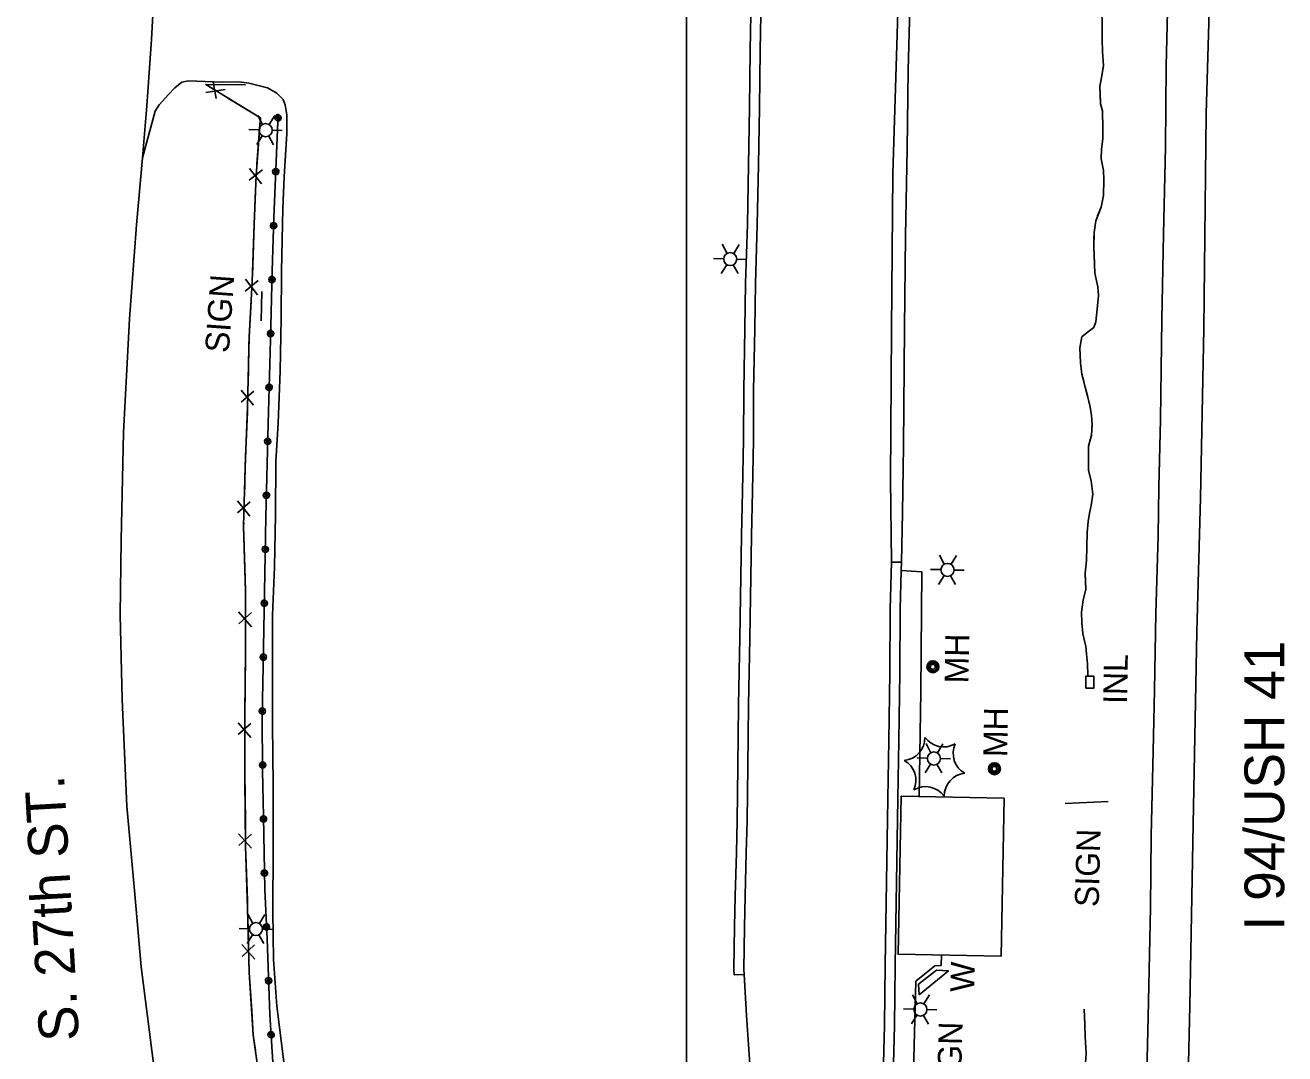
# Model space of a CAD drawing. Extents: x 591954 to 597000, y 198576 to 213500.
# Drawn here: x 593833.7 to 594150.4, y 210712.6 to 210971.1 of the extents above; entities that cross this region are included whole.
import ezdxf

# ---------------------------------------------------------------- set-up
doc = ezdxf.new("R2010")
doc.units = 0
for name, color, linetype in [('1', 7, 'Continuous'), ('Level 10', 7, 'Continuous'), ('Level 11', 7, 'Continuous'), ('Level 12', 7, 'Continuous'), ('Level 14', 7, 'Continuous'), ('Level 15', 7, 'Continuous'), ('Level 16', 7, 'Continuous'), ('Level 17', 7, 'Continuous'), ('Level 18', 7, 'Continuous'), ('Level 19', 7, 'Continuous')]:
    doc.layers.add(name, color=color, linetype=linetype)

msp = doc.modelspace()

# ---------------------------------------------------------------- linework, layer by layer
at = {"layer": 'Level 10'}
msp.add_line((594000, 210000), (594000, 211500), dxfattribs=at)
at = {"layer": 'Level 11'}
for points in [[(594121.44, 210459.17), (594122.25, 210498.37), (594123.17, 210553.35), (594124.43, 210619.5), (594125, 210654.8), (594125.89, 210695.68), (594126.54, 210724.61), (594127.4, 210770.31), (594128.28, 210818.66), (594129.2, 210852.3), (594130.02, 210894.89), (594130.64, 210948.86), (594131.88, 210991.76), (594132.98, 211045.17), (594133.71, 211089.02), (594134.68, 211134.48), (594135.32, 211176), (594136.16, 211221.31), (594137.06, 211262.73), (594137.74, 211300.23), (594138.56, 211351.93)], [(594104.77, 211349.8), (594099.35, 211323.85), (594093.93, 211299.6), (594085.43, 211259.76), (594076, 211209.29), (594068.36, 211162.42), (594064.4, 211134.4), (594060.86, 211102.94), (594058.46, 211075.99), (594056.32, 211045.98), (594054.89, 211024.24), (594053.66, 210994.17), (594052.93, 210968.84), (594051.87, 210933.79), (594051.53, 210894.51), (594051.26, 210856.92), (594051.49, 210836.18)], [(593863.15, 210937.74), (593864.28, 210950.85), (593865.4, 210967.49), (593866.62, 210989.24), (593867.33, 210996.42)], [(594014.42, 210732.48), (594014.39, 210733.85), (594014.57, 210744.41), (594014.72, 210752.24), (594015, 210763.12), (594015.21, 210771.1), (594015.38, 210784.79), (594015.52, 210800.21), (594015.85, 210817.05), (594016.3, 210842.78), (594016.56, 210853.97), (594016.79, 210866.85), (594016.84, 210879.33), (594017.12, 210894.76), (594017.3, 210906.19), (594017.77, 210920.93), (594018.05, 210935.99), (594018.28, 210950.31), (594018.46, 210964.8), (594018.71, 210978.26)], [(594015.96, 210964.84), (594016.21, 210978.31)], [(594015.96, 210964.84), (594016.21, 210978.31)], [(594053.99, 210836.12), (594054.29, 210848.54), (594054.54, 210865.38), (594054.75, 210894.94), (594055, 210918.2), (594055.46, 210940.01), (594055.68, 210959.83), (594056.21, 210978.5)], [(594120.95, 210978.02), (594120.6, 210960.88), (594120.4, 210940.43), (594119.89, 210918.56), (594119.5, 210897.15)], [(594015.78, 210950.34), (594015.96, 210964.84)], [(594015.78, 210950.34), (594015.96, 210964.84)], [(594015.55, 210936.03), (594015.78, 210950.34)], [(594015.55, 210936.03), (594015.78, 210950.34)], [(593942.07, 210448.25), (593930.85, 210481.68), (593922.36, 210504.92), (593910.35, 210541.32), (593899.7, 210573.1), (593890.09, 210602.43), (593883.59, 210625.68), (593877.84, 210646.9), (593873.2, 210666.64), (593869.3, 210687.68), (593866.01, 210709.44), (593862.8, 210734.46), (593861.17, 210753.61), (593859.27, 210774.78), (593858.05, 210801.65), (593857.58, 210822.9), (593857.85, 210841.64), (593858.43, 210868.75), (593859.89, 210897.29), (593861.7, 210920.91), (593863.15, 210937.74)], [(594015.27, 210920.99), (594015.55, 210936.03)], [(594015.27, 210920.99), (594015.55, 210936.03)], [(594014.8, 210906.25), (594015.27, 210920.99)], [(594014.8, 210906.25), (594015.27, 210920.99)], [(594014.62, 210894.8), (594014.8, 210906.25)], [(594014.62, 210894.8), (594014.8, 210906.25)], [(594119.5, 210897.15), (594119.11, 210872.03), (594118.75, 210854.96), (594118.55, 210842.77), (594117.96, 210823.25), (594117.65, 210803.96), (594117.31, 210788.66), (594116.78, 210767.34), (594116.67, 210749.31), (594116.07, 210721.82), (594115.43, 210697.32), (594115.23, 210679.05), (594114.7, 210660.36), (594114.36, 210644.35), (594114.05, 210623.86), (594113.82, 210608.1), (594113.47, 210586.67), (594113.12, 210567.42), (594112.64, 210548.64), (594112.24, 210528.59), (594111.95, 210511.33), (594111.37, 210491), (594111.28, 210469.69), (594111.11, 210459.41)], [(594014.34, 210879.36), (594014.62, 210894.8)], [(594014.34, 210879.36), (594014.62, 210894.8)], [(594014.29, 210866.88), (594014.34, 210879.36)], [(594014.29, 210866.88), (594014.34, 210879.36)], [(594014.06, 210854.02), (594014.29, 210866.88)], [(594014.06, 210854.02), (594014.29, 210866.88)], [(594013.8, 210842.84), (594014.06, 210854.02)], [(594013.8, 210842.84), (594014.06, 210854.02)], [(594013.35, 210817.09), (594013.8, 210842.84)], [(594013.35, 210817.09), (594013.8, 210842.84)], [(594051.49, 210836.18), (594051.21, 210824.34), (594051.08, 210808.43), (594050.81, 210791.35), (594050.62, 210776.77), (594049.9, 210734.81), (594049.73, 210719.74), (594049.4, 210706.94), (594049.33, 210700.84), (594049.22, 210695.93)], [(594051.49, 210836.18), (594053.89, 210836.13), (594053.99, 210836.12), (594053.94, 210834.04)], [(594053.94, 210834.04), (594053.71, 210824.3), (594053.58, 210808.4), (594053.31, 210791.31), (594053.12, 210776.73), (594052.4, 210734.78), (594052.23, 210719.69), (594051.9, 210706.9), (594051.83, 210700.8), (594051.72, 210695.87)], [(594013.02, 210800.24), (594013.35, 210817.09)], [(594013.02, 210800.24), (594013.35, 210817.09)], [(594012.88, 210784.81), (594013.02, 210800.24)], [(594012.88, 210784.81), (594013.02, 210800.24)], [(594012.71, 210771.15), (594012.88, 210784.81)], [(594012.71, 210771.15), (594012.88, 210784.81)], [(594012.5, 210763.18), (594012.71, 210771.15)], [(594012.5, 210763.18), (594012.71, 210771.15)], [(594012.22, 210752.3), (594012.5, 210763.18)], [(594012.22, 210752.3), (594012.5, 210763.18)], [(594012.07, 210744.46), (594012.22, 210752.3)], [(594012.07, 210744.46), (594012.22, 210752.3)], [(594011.89, 210733.84), (594012.07, 210744.46)], [(594011.89, 210733.84), (594012.07, 210744.46)], [(594011.92, 210732.43), (594011.89, 210733.84)], [(594011.92, 210732.43), (594011.89, 210733.84)], [(594014.42, 210732.48), (594012.02, 210732.44), (594011.92, 210732.43)], [(594026.41, 210581.46), (594024.84, 210592.23), (594023.17, 210610.08), (594022.08, 210626.74), (594021.09, 210639.08), (594019.43, 210662.48), (594016.8, 210696.59), (594015.07, 210722.2), (594014.42, 210732.48)]]:
    msp.add_lwpolyline(points, dxfattribs=at)
at = {"layer": 'Level 12'}
msp.add_lwpolyline([(594079.87, 210776.86), (594079.11, 210737.11), (594053.19, 210737.61), (594053.95, 210777.35), (594079.87, 210776.86)], dxfattribs=at)
at = {"layer": 'Level 14'}
for p, q in [((593893.34, 210946.16), (593892.15, 210948.46)), ((593895.05, 210946.15), (593896.41, 210948.38)), ((593892.51, 210944.8), (593889.91, 210944.87)), ((593893.27, 210943.3), (593891.9, 210941.11)), ((593894.9, 210943.26), (593896.15, 210941.08)), ((593895.78, 210944.71), (593898.3, 210944.64)), ((594010.15, 210913.76), (594008.95, 210916.06)), ((594011.85, 210913.75), (594013.22, 210915.98)), ((594009.32, 210912.4), (594006.71, 210912.47)), ((594012.59, 210912.3), (594015.11, 210912.24)), ((594010.07, 210910.9), (594008.71, 210908.71)), ((594011.71, 210910.86), (594012.95, 210908.68)), ((594064.79, 210835.62), (594063.59, 210837.92)), ((594066.49, 210835.61), (594067.85, 210837.84)), ((594063.95, 210834.26), (594061.35, 210834.33)), ((594064.71, 210832.76), (594063.35, 210830.57)), ((594066.34, 210832.72), (594067.59, 210830.54)), ((594067.23, 210834.16), (594069.75, 210834.1)), ((594061.39, 210788.23), (594060.19, 210790.53)), ((594063.09, 210788.22), (594064.45, 210790.45)), ((594060.55, 210786.86), (594057.95, 210786.94)), ((594061.31, 210785.37), (594059.94, 210783.18)), ((594062.94, 210785.33), (594064.19, 210783.15)), ((594063.82, 210786.77), (594066.34, 210786.71)), ((593890.9, 210745.36), (593889.7, 210747.66)), ((593892.6, 210745.35), (593893.96, 210747.58)), ((593890.06, 210743.99), (593887.46, 210744.07)), ((593893.34, 210743.9), (593895.86, 210743.84)), ((593890.82, 210742.5), (593889.46, 210740.31)), ((593892.45, 210742.46), (593893.7, 210740.28)), ((594057.97, 210725.13), (594056.77, 210727.43)), ((594059.67, 210725.12), (594061.04, 210727.35)), ((594057.13, 210723.77), (594054.53, 210723.84)), ((594057.89, 210722.28), (594056.53, 210720.09)), ((594059.53, 210722.23), (594060.77, 210720.05)), ((594060.41, 210723.68), (594062.93, 210723.61))]:
    msp.add_line(p, q, dxfattribs=at)
for points in [[(593892.98, 210896.77), (593893.17, 210904.19)], [(594105.99, 210775.96), (594095.2, 210775.52)]]:
    msp.add_lwpolyline(points, dxfattribs=at)
for centre in [(593894.14, 210944.73), (594010.95, 210912.33), (594065.59, 210834.19), (594062.18, 210786.8), (593891.7, 210743.93), (594058.77, 210723.7)]:
    msp.add_circle(centre, 1.64, dxfattribs=at)
at = {"layer": 'Level 15'}
for p, q in [((593880.95, 210956.83), (593881.68, 210952.67)), ((593879.11, 210954.16), (593883.97, 210954.98)), ((593893.31, 210934.74), (593889.98, 210932.14)), ((593890.09, 210935.1), (593893.11, 210931.21)), ((593892.26, 210906.92), (593888.95, 210904.29)), ((593889.04, 210907.25), (593892.08, 210903.37)), ((593887.96, 210879.37), (593891.11, 210875.58)), ((593891.19, 210879.12), (593887.96, 210876.4)), ((593890.28, 210851.27), (593887.03, 210848.56)), ((593887.05, 210851.53), (593890.18, 210847.73)), ((593887.33, 210823.64), (593890.55, 210819.91)), ((593890.57, 210823.46), (593887.39, 210820.67)), ((593887.2, 210795.77), (593890.43, 210792.05)), ((593890.43, 210795.6), (593887.26, 210792.81)), ((593887.33, 210767.89), (593890.62, 210764.22)), ((593890.57, 210767.76), (593887.43, 210764.93)), ((593888.11, 210740.02), (593891.44, 210736.39)), ((593891.35, 210739.93), (593888.25, 210737.05))]:
    msp.add_line(p, q, dxfattribs=at)
for points in [[(593889.06, 210956.14), (593879.07, 210956.23), (593892.83, 210947.81), (593891.73, 210933.39), (593891.23, 210921.11), (593890.75, 210906.69), (593890, 210892.79), (593889.6, 210875.1), (593889.02, 210860.04), (593888.61, 210845.19), (593889.09, 210828.85), (593889.03, 210812.68), (593888.94, 210797.15), (593888.93, 210781.49), (593889.11, 210764.75), (593889.6, 210749.07), (593890.03, 210733.04), (593891.01, 210717.34), (593892.91, 210703.57)], [(593889.06, 210956.14), (593879.11, 210956.23)], [(593884.64, 210952.81), (593892.83, 210947.81), (593892.7, 210946.09)], [(593892.7, 210946.09), (593891.94, 210936.16)], [(593891.57, 210929.59), (593891.23, 210921.11), (593891.14, 210918.27)], [(593891.14, 210918.27), (593890.81, 210908.32)], [(593890.49, 210901.75), (593890, 210892.79), (593889.95, 210890.44)], [(593889.95, 210890.44), (593889.72, 210880.49)], [(593889.55, 210873.91), (593889.11, 210862.6)], [(593889.11, 210862.6), (593889.02, 210860.04), (593888.82, 210852.64)], [(593888.64, 210846.06), (593888.61, 210845.19), (593888.92, 210834.75)], [(593888.92, 210834.75), (593889.09, 210828.85), (593889.07, 210824.79)], [(593889.05, 210818.21), (593889.03, 210812.68), (593888.99, 210806.89)], [(593888.99, 210806.89), (593888.94, 210797.15), (593888.94, 210796.93)], [(594100.4, 210804.49), (594102.4, 210804.48), (594102.41, 210807.48), (594100.41, 210807.49), (594100.4, 210804.49)], [(593888.93, 210790.35), (593888.93, 210781.49), (593888.96, 210779.03)], [(593888.96, 210779.03), (593889.06, 210769.07)], [(593889.18, 210762.49), (593889.54, 210751.18)], [(593889.54, 210751.18), (593889.6, 210749.07), (593889.81, 210741.22)], [(593889.99, 210734.64), (593890.03, 210733.04), (593890.64, 210723.34)], [(594058.46, 210727.36), (594065.8, 210733.41), (594062.83, 210733.62), (594058.28, 210730.06), (594058.46, 210727.36)], [(593890.64, 210723.34), (593891.01, 210717.34), (593891.55, 210713.43)]]:
    msp.add_lwpolyline(points, dxfattribs=at)
at = {"layer": 'Level 16'}
for centre, radius in [((594061.92, 210809.85), 1.5), ((594061.92, 210809.85), 1.22), ((594061.92, 210809.83), 0.968), ((594061.89, 210809.83), 0.605), ((594077.4, 210784.22), 1.5), ((594077.4, 210784.22), 1.22), ((594077.4, 210784.21), 0.968), ((594077.37, 210784.2), 0.605)]:
    msp.add_circle(centre, radius, dxfattribs=at)
at = {"layer": 'Level 17'}
for points in [[(593898.52, 210952.46), (593896.93, 210954.06), (593894.63, 210955.34), (593889.87, 210956.58), (593887.52, 210956.86), (593883.21, 210956.82), (593878.89, 210957), (593874.73, 210957.1), (593873.1, 210956.77), (593871.32, 210955.35), (593869.73, 210953.72), (593867.35, 210951.13), (593866.39, 210949.52), (593863.15, 210937.74)], [(593898.72, 210710.58), (593896.98, 210724.55), (593896.11, 210736.27), (593895.97, 210748.3), (593896.05, 210764.38), (593895.99, 210780.23), (593895.89, 210795.28), (593895.87, 210808.62), (593895.9, 210822.81), (593896.33, 210834.9), (593896.63, 210848.03), (593896.73, 210861.43), (593897.27, 210871.12), (593897.78, 210884.25), (593898.07, 210897.43), (593898.12, 210909.27), (593898.43, 210925.01), (593898.77, 210932.98), (593899.44, 210943.89), (593899.5, 210948.62), (593899.08, 210951.11), (593898.52, 210952.46)], [(593897.28, 210948.84), (593896.2, 210922.74), (593895.77, 210909.28), (593895.33, 210892.01), (593894.75, 210870.88), (593894.21, 210847.52), (593893.88, 210828.64), (593893.49, 210810.04), (593893.29, 210797.38), (593893.38, 210783.8), (593893.58, 210772.21), (593893.91, 210753.86), (593894.49, 210741.5), (593895.19, 210722.44), (593895.95, 210710.45)], [(593897.28, 210948.84), (593896.2, 210922.74), (593895.77, 210909.28), (593895.33, 210892.01), (593894.75, 210870.88), (593894.21, 210847.52), (593893.88, 210828.64), (593893.49, 210810.04), (593893.29, 210797.38), (593893.38, 210783.8), (593893.58, 210772.21), (593893.91, 210753.86), (593894.49, 210741.5), (593895.19, 210722.44), (593895.95, 210710.45)], [(594053.94, 210834.04), (594059.13, 210833.7), (594058.84, 210803.66), (594058.5, 210777.26)], [(594057.17, 210695.11), (594057.1, 210711.3), (594057.6, 210730.79), (594062.4, 210734.67), (594063.96, 210734.73), (594064.07, 210737.4)]]:
    msp.add_lwpolyline(points, dxfattribs=at)
for centre, major_axis, ratio in [((593897.24, 210947.84), (0.789, -0.032), 0.999581), ((593897.24, 210947.84), (-0.06, -0.394), 0.99914), ((593896.68, 210934.29), (-0.033, -0.789), 0.99976), ((593896.68, 210934.29), (0.393, -0.061), 0.999657), ((593896.13, 210920.74), (0.789, -0.025), 0.999868), ((593896.13, 210920.74), (0.394, -0.056), 0.999237), ((593895.72, 210907.18), (-0.02, -0.79), 0.999679), ((593895.72, 210907.18), (-0.054, -0.394), 0.999684), ((593895.38, 210893.62), (0.789, -0.02), 0.999688), ((593895.38, 210893.62), (0.394, -0.054), 0.999059), ((593895.01, 210880.07), (0.789, -0.021), 0.999738), ((593895.01, 210880.07), (0.394, -0.054), 0.999091), ((593894.65, 210866.51), (-0.018, -0.79), 0.999726), ((593894.65, 210866.51), (-0.053, -0.394), 0.999715), ((593894.34, 210852.95), (-0.018, -0.79), 0.99974), ((593894.34, 210852.95), (-0.053, -0.395), 0.999744), ((593894.07, 210839.39), (0.79, -0.014), 0.999524), ((593894.07, 210839.39), (-0.051, -0.395), 0.999845), ((593893.82, 210825.83), (0.79, -0.016), 0.999585), ((593893.82, 210825.83), (-0.052, -0.395), 0.999771), ((593893.54, 210812.27), (0.79, -0.016), 0.999585), ((593893.54, 210812.27), (0.394, -0.052), 0.998971), ((593893.31, 210798.71), (0.79, -0.012), 0.999492), ((593893.31, 210798.71), (0.395, -0.05), 0.998876), ((593893.37, 210785.14), (0.005, -0.79), 0.99998), ((593893.37, 210785.14), (-0.041, -0.396), 0.999972), ((593893.6, 210771.58), (0.014, -0.79), 0.999843), ((593893.6, 210771.58), (-0.037, -0.396), 0.999845), ((593893.83, 210758.02), (0.014, -0.79), 0.999843), ((593893.83, 210758.02), (-0.037, -0.396), 0.999845), ((593894.35, 210744.47), (0.789, 0.038), 0.999862), ((593894.35, 210744.47), (-0.025, -0.398), 0.998919), ((593894.88, 210730.92), (0.029, -0.789), 0.999958), ((593894.88, 210730.92), (0.397, -0.029), 0.999408), ((593895.51, 210717.37), (0.05, -0.788), 0.999893), ((593895.51, 210717.37), (-0.019, -0.398), 0.99928)]:
    msp.add_ellipse(centre, major_axis=major_axis, ratio=ratio, dxfattribs=at)
at = {"layer": 'Level 18'}
for centre, start, end in [((594054.19, 210792.01), 275.2113, 0.9762), ((594064.59, 210795.41), 215.2113, 300.9762), ((594072.73, 210788.1), 155.2113, 240.9762), ((594051.93, 210781.3), 335.2113, 60.9762), ((594070.48, 210777.39), 95.2113, 180.9762), ((594060.08, 210774), 35.2113, 120.9762)]:
    msp.add_arc(centre, 5.72, start, end, dxfattribs=at)
at = {"layer": 'Level 19'}
for points in [[(594104.05, 210951.8), (594103.86, 210955.67), (594104.33, 210957.96), (594104.8, 210960.93), (594104.72, 210962.15), (594104.6, 210964.51), (594104.45, 210967.53), (594104.5, 210972.25), (594104.35, 210975.27), (594104.15, 210978.85), (594104.12, 210980.69)], [(594104.5, 210972.25), (594104.45, 210967.53), (594104.6, 210964.51), (594104.72, 210962.15), (594104.8, 210960.93), (594104.33, 210957.96), (594103.86, 210955.67), (594104.07, 210951.34), (594104.57, 210949.56), (594104.61, 210945.13), (594104.64, 210942.57), (594104.35, 210939.97), (594104.2, 210937.52), (594104.79, 210934.58), (594104.93, 210932.29), (594104.84, 210928.31), (594104.2, 210925.38), (594102.86, 210921.93), (594102.43, 210919), (594102.4, 210915.44), (594102.65, 210908.78)], [(594103.34, 210923.18), (594104.2, 210925.38), (594104.84, 210928.31), (594104.93, 210932.29), (594104.79, 210934.58), (594104.2, 210937.52), (594104.35, 210939.97), (594104.64, 210942.57), (594104.61, 210945.13), (594104.57, 210949.56), (594104.07, 210951.34), (594104.05, 210951.8)], [(594102.41, 210917.3), (594102.43, 210919), (594102.47, 210919.3)], [(594102.55, 210911.3), (594102.48, 210913.3)], [(594102.65, 210908.78), (594103.42, 210905.34), (594103.52, 210903.19), (594103.27, 210900.56), (594103.08, 210898.12), (594102.85, 210896.55), (594102.35, 210895.17), (594100.69, 210893.9), (594099.36, 210892.75), (594098.9, 210890.05), (594099.01, 210886.24), (594099.36, 210883.42), (594100.18, 210880.16), (594100.87, 210877.65), (594101.35, 210875.54), (594101.79, 210873.08), (594101.96, 210870.76), (594101.76, 210868.04), (594101.02, 210865.31), (594101.08, 210859.16), (594101.69, 210856.55), (594102.1, 210853.22), (594101.71, 210850.43), (594101.31, 210848.48), (594100.94, 210846.38), (594100.69, 210843.57), (594100.6, 210839.98), (594100.52, 210836.54), (594100.24, 210833.36), (594100.34, 210829.28), (594099.67, 210826.66), (594099.32, 210823.59), (594099.34, 210820.88), (594099.62, 210818.18), (594100.03, 210816.33), (594100.36, 210814.96), (594100.51, 210813.11), (594100.79, 210810.59), (594100.85, 210807.77)], [(594099.83, 210881.55), (594099.36, 210883.42), (594099.01, 210886.24), (594098.9, 210890.05), (594099.36, 210892.75), (594100.69, 210893.9), (594102.35, 210895.17), (594102.85, 210896.55), (594103.08, 210898.12), (594103.27, 210900.56), (594103.52, 210903.19), (594103.42, 210905.34), (594102.65, 210908.78)], [(594101.31, 210875.74), (594100.87, 210877.65), (594100.86, 210877.68)], [(594101.89, 210869.79), (594101.96, 210870.76), (594101.89, 210871.78)], [(594101.04, 210863.89), (594101.02, 210865.31), (594101.17, 210865.87)], [(594100.3, 210831.11), (594100.24, 210833.36), (594100.52, 210836.54), (594100.6, 210839.98), (594100.69, 210843.57), (594100.94, 210846.38), (594101.31, 210848.48), (594101.71, 210850.43), (594102.1, 210853.22), (594101.69, 210856.55), (594101.08, 210859.16), (594101.08, 210859.89)], [(594100.85, 210807.77), (594100.79, 210810.59), (594100.51, 210813.11), (594100.36, 210814.96), (594100.03, 210816.33), (594099.62, 210818.18), (594099.34, 210820.88), (594099.32, 210823.59), (594099.67, 210826.66), (594100.34, 210829.28), (594100.3, 210831.11)], [(594098.91, 210694.99), (594098.56, 210697.2), (594098.51, 210700.67), (594099.03, 210702.38), (594099.33, 210704.14), (594099.53, 210706.54), (594100.3, 210710.28), (594100.44, 210712.61), (594100.24, 210716.91), (594100.11, 210719.93), (594099.97, 210723.76)], [(594099.97, 210723.76), (594100.11, 210719.93), (594100.24, 210716.91), (594100.44, 210712.61), (594100.3, 210710.28)]]:
    msp.add_lwpolyline(points, dxfattribs=at)

# ---------------------------------------------------------------- texts
at = {"layer": '1'}
for s, rotation, p in [('I 94/USH 41', 90, (594150.26, 210743.58)), ('S. 27th ST.', 93.2719, (593847.25, 210715.99))]:
    msp.add_text(s, height=10, rotation=rotation, dxfattribs=at).set_placement(p)
at = {"layer": 'Level 14'}
for rotation, p in [(85.9129, (593884.87, 210888.63)), (88.536, (594103.59, 210749.41)), (88.536, (594068.89, 210700.93))]:
    msp.add_text('SIGN', height=6, rotation=rotation, dxfattribs=at).set_placement(p)
at = {"layer": 'Level 15'}
for s, rotation, p in [('INL', 89.0379, (594110.74, 210800.47)), ('W', 89.0748, (594072.32, 210728.09))]:
    msp.add_text(s, height=6, rotation=rotation, dxfattribs=at).set_placement(p)
at = {"layer": 'Level 16'}
for p in [(594070.85, 210805.64), (594080.59, 210787.12)]:
    msp.add_text('MH', height=6, rotation=89.0379, dxfattribs=at).set_placement(p)

doc.saveas('drawing.dxf')
